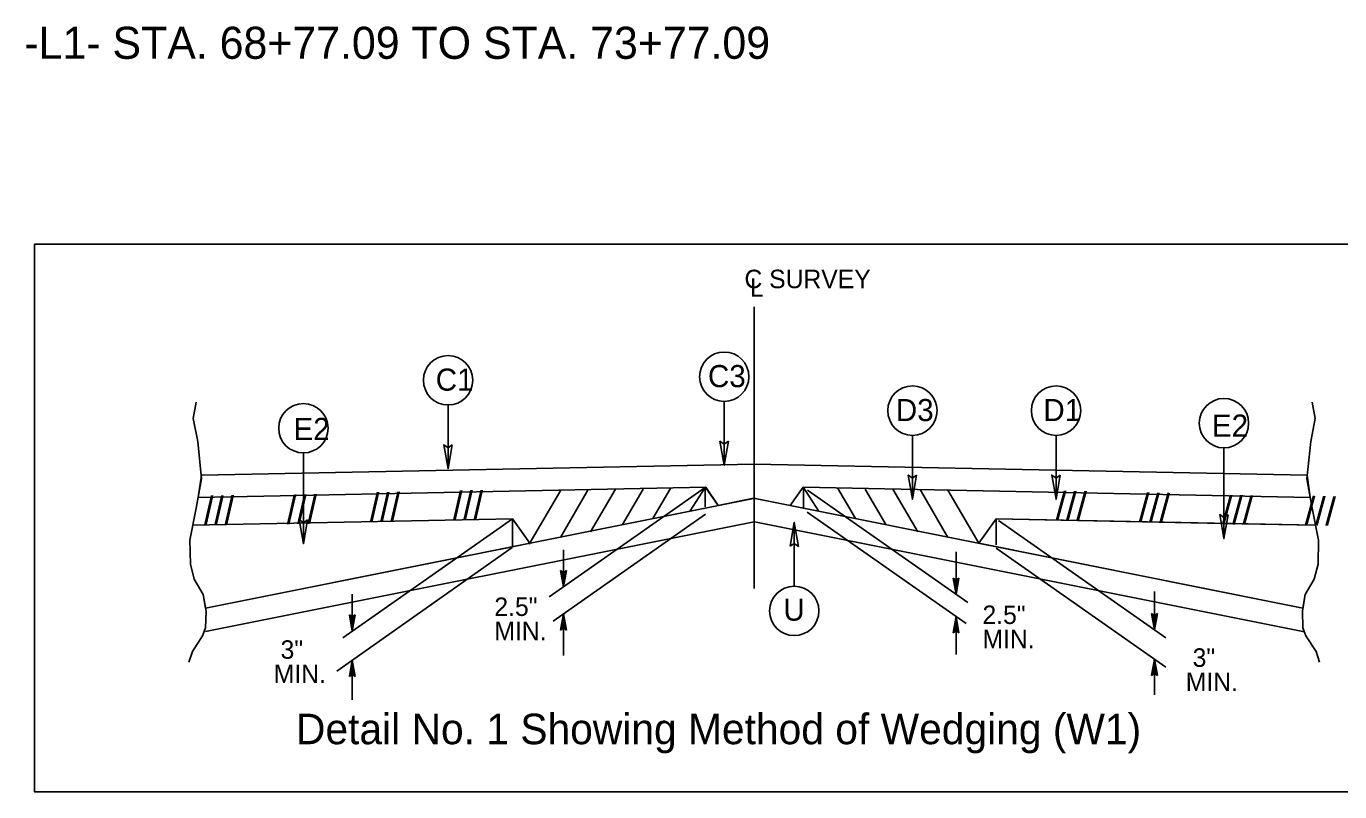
# Model space of a CAD drawing. Extents: x 573813 to 575363, y -54752 to -53123.
# Drawn here: x 574725.3 to 574799.8, y -53244.6 to -53201.2 of the extents above; entities that cross this region are included whole.
import ezdxf

# ---------------------------------------------------------------- set-up
doc = ezdxf.new("R2010")
doc.units = 0
for name, color, linetype in [('Old_Level_1', 7, 'Continuous'), ('Prop Pavement Schedule Description CELL', 7, 'Continuous'), ('Typical Detail Wedge2 CELL', 7, 'Continuous'), ('Typical ID Circle CELL', 7, 'Continuous'), ('Typical Terminator CELL', 7, 'Continuous'), ('Typical Text Centerline CELL', 7, 'Continuous'), ('Typical Text General CELL', 7, 'Continuous'), ('Typical Text ID Circle CELL', 7, 'Continuous')]:
    doc.layers.add(name, color=color, linetype=linetype)

msp = doc.modelspace()

# ---------------------------------------------------------------- linework, layer by layer
at = {"layer": 'Prop Pavement Schedule Description CELL'}
msp.add_lwpolyline([(574725.715, -53213.526), (574805.217, -53213.526), (574805.217, -53244.59), (574725.715, -53244.59)], close=True, dxfattribs=at)
at = {"layer": 'Typical Detail Wedge2 CELL'}
for p, q in [((574766.569, -53233.07), (574766.569, -53217.083)), ((574766.569, -53233.07), (574766.569, -53222.151)), ((574735.013, -53227.895), (574735.192, -53226.634)), ((574766.568, -53226.007), (574735.192, -53226.634)), ((574735.192, -53226.634), (574766.568, -53226.007)), ((574766.568, -53226.007), (574797.946, -53226.634)), ((574766.571, -53226.007), (574797.946, -53226.634)), ((574797.946, -53226.634), (574798.126, -53227.895)), ((574763.815, -53227.319), (574735.013, -53227.895)), ((574763.815, -53227.319), (574735.013, -53227.895)), ((574763.78, -53227.342), (574754.939, -53233.534)), ((574758.702, -53227.422), (574757.285, -53229.85)), ((574760.264, -53227.425), (574759.089, -53229.436)), ((574761.838, -53227.344), (574760.815, -53229.099)), ((574762.924, -53228.661), (574763.775, -53227.331)), ((574763.775, -53227.331), (574763.775, -53228.424)), ((574764.52, -53228.353), (574763.815, -53227.319)), ((574763.815, -53227.352), (574764.52, -53228.353)), ((574769.344, -53227.319), (574768.616, -53228.353)), ((574769.344, -53227.319), (574768.616, -53228.353)), ((574769.298, -53227.342), (574769.343, -53227.344)), ((574769.344, -53227.319), (574798.126, -53227.895)), ((574798.126, -53227.895), (574769.344, -53227.319)), ((574770.214, -53228.661), (574769.362, -53227.331)), ((574769.362, -53227.331), (574769.362, -53228.535)), ((574771.298, -53227.344), (574772.322, -53229.099)), ((574772.873, -53227.425), (574774.047, -53229.436)), ((574774.434, -53227.422), (574775.852, -53229.85)), ((574766.615, -53227.936), (574735.427, -53234.175)), ((574755.586, -53227.484), (574753.803, -53230.54)), ((574757.152, -53227.452), (574755.574, -53230.161)), ((574766.521, -53227.936), (574764.52, -53228.353)), ((574766.521, -53227.936), (574797.711, -53234.175)), ((574768.616, -53228.353), (574766.521, -53227.936)), ((574769.584, -53227.486), (574778.692, -53233.865)), ((574775.985, -53227.452), (574777.564, -53230.161)), ((574777.552, -53227.484), (574779.308, -53230.495)), ((574763.8, -53228.855), (574755.149, -53234.912)), ((574769.571, -53228.726), (574778.59, -53235.041)), ((574752.842, -53229.112), (574734.707, -53229.475)), ((574734.707, -53229.475), (574752.842, -53229.112)), ((574766.556, -53229.279), (574735.416, -53235.508)), ((574752.842, -53229.112), (574743.213, -53235.855)), ((574753.828, -53230.498), (574752.842, -53229.112)), ((574752.842, -53229.112), (574752.842, -53230.694)), ((574752.842, -53229.112), (574753.826, -53230.495)), ((574766.58, -53229.279), (574797.793, -53235.523)), ((574780.294, -53229.112), (574779.308, -53230.495)), ((574779.31, -53230.495), (574780.294, -53229.112)), ((574780.294, -53229.112), (574798.43, -53229.475)), ((574780.294, -53229.112), (574780.294, -53230.582)), ((574793.228, -53229.371), (574780.294, -53229.112)), ((574780.441, -53229.214), (574789.938, -53235.865)), ((574798.43, -53229.475), (574793.228, -53229.371)), ((574752.834, -53230.744), (574742.88, -53237.749)), ((574752.842, -53230.692), (574749.684, -53231.324)), ((574753.826, -53230.495), (574752.842, -53230.692)), ((574755.744, -53230.866), (574755.744, -53232.969)), ((574778.026, -53230.987), (574778.026, -53233.398)), ((574779.308, -53230.495), (574783.454, -53231.324)), ((574780.294, -53230.774), (574789.922, -53237.518)), ((574749.684, -53231.324), (574735.427, -53234.175)), ((574783.454, -53231.324), (574797.711, -53234.175)), ((574755.744, -53232.969), (574755.582, -53232.047)), ((574755.744, -53232.167), (574755.582, -53232.047)), ((574755.744, -53232.969), (574755.605, -53232.065)), ((574755.628, -53232.082), (574755.744, -53232.969)), ((574755.744, -53232.969), (574755.651, -53232.098)), ((574755.675, -53232.115), (574755.744, -53232.969)), ((574755.744, -53232.969), (574755.698, -53232.133)), ((574755.721, -53232.15), (574755.744, -53232.969)), ((574755.744, -53232.969), (574755.908, -53232.047)), ((574755.908, -53232.047), (574755.744, -53232.167)), ((574755.885, -53232.065), (574755.744, -53232.969)), ((574755.744, -53232.969), (574755.86, -53232.082)), ((574755.837, -53232.098), (574755.744, -53232.969)), ((574755.744, -53232.969), (574755.814, -53232.115)), ((574755.79, -53232.133), (574755.744, -53232.969)), ((574755.744, -53232.969), (574755.767, -53232.15)), ((574755.744, -53232.167), (574755.744, -53232.969)), ((574778.026, -53233.398), (574777.864, -53232.475)), ((574778.026, -53232.595), (574777.864, -53232.475)), ((574778.026, -53233.398), (574777.887, -53232.492)), ((574777.91, -53232.51), (574778.026, -53233.398)), ((574778.026, -53233.398), (574777.933, -53232.527)), ((574777.956, -53232.544), (574778.026, -53233.398)), ((574778.026, -53233.398), (574777.979, -53232.561)), ((574778.002, -53232.578), (574778.026, -53233.398)), ((574778.026, -53233.398), (574778.189, -53232.475)), ((574778.189, -53232.475), (574778.026, -53232.595)), ((574778.165, -53232.492), (574778.026, -53233.398)), ((574778.026, -53233.398), (574778.142, -53232.51)), ((574778.119, -53232.527), (574778.026, -53233.398)), ((574778.026, -53233.398), (574778.096, -53232.544)), ((574778.072, -53232.561), (574778.026, -53233.398)), ((574778.026, -53233.398), (574778.049, -53232.578)), ((574778.026, -53232.595), (574778.026, -53233.398)), ((574743.755, -53233.379), (574743.755, -53235.476)), ((574789.286, -53233.227), (574789.286, -53235.407)), ((574743.755, -53235.476), (574743.591, -53234.554)), ((574743.755, -53234.673), (574743.591, -53234.554)), ((574743.755, -53235.476), (574743.614, -53234.57)), ((574743.64, -53234.588), (574743.755, -53235.476)), ((574743.755, -53235.476), (574743.663, -53234.604)), ((574743.686, -53234.621), (574743.755, -53235.476)), ((574743.755, -53235.476), (574743.709, -53234.638)), ((574743.732, -53234.655), (574743.755, -53235.476)), ((574743.755, -53235.476), (574743.918, -53234.554)), ((574743.918, -53234.554), (574743.755, -53234.673)), ((574743.895, -53234.57), (574743.755, -53235.476)), ((574743.755, -53235.476), (574743.872, -53234.588)), ((574743.848, -53234.604), (574743.755, -53235.476)), ((574743.755, -53235.476), (574743.824, -53234.621)), ((574743.802, -53234.638), (574743.755, -53235.476)), ((574743.755, -53235.476), (574743.778, -53234.655)), ((574743.755, -53234.673), (574743.755, -53235.476)), ((574755.744, -53234.496), (574755.582, -53235.419)), ((574755.605, -53235.4), (574755.744, -53234.496)), ((574755.744, -53234.496), (574755.628, -53235.384)), ((574755.651, -53235.366), (574755.744, -53234.496)), ((574755.744, -53234.496), (574755.675, -53235.35)), ((574755.698, -53235.333), (574755.744, -53234.496)), ((574755.744, -53234.496), (574755.721, -53235.316)), ((574755.744, -53234.496), (574755.744, -53236.864)), ((574755.744, -53234.496), (574755.908, -53235.419)), ((574755.744, -53235.299), (574755.744, -53234.496)), ((574755.767, -53235.316), (574755.744, -53234.496)), ((574755.744, -53234.496), (574755.79, -53235.333)), ((574755.814, -53235.35), (574755.744, -53234.496)), ((574755.744, -53234.496), (574755.837, -53235.366)), ((574755.86, -53235.384), (574755.744, -53234.496)), ((574755.744, -53234.496), (574755.885, -53235.4)), ((574778.026, -53234.646), (574777.864, -53235.569)), ((574777.887, -53235.55), (574778.026, -53234.646)), ((574778.026, -53234.646), (574777.91, -53235.534)), ((574777.933, -53235.516), (574778.026, -53234.646)), ((574778.026, -53234.646), (574777.956, -53235.5)), ((574777.979, -53235.483), (574778.026, -53234.646)), ((574778.026, -53234.646), (574778.002, -53235.466)), ((574778.026, -53234.646), (574778.026, -53236.803)), ((574778.026, -53234.646), (574778.189, -53235.569)), ((574778.026, -53235.449), (574778.026, -53234.646)), ((574778.049, -53235.466), (574778.026, -53234.646)), ((574778.026, -53234.646), (574778.072, -53235.483)), ((574778.096, -53235.5), (574778.026, -53234.646)), ((574778.026, -53234.646), (574778.119, -53235.516)), ((574778.142, -53235.534), (574778.026, -53234.646)), ((574778.026, -53234.646), (574778.165, -53235.55)), ((574789.286, -53235.407), (574789.123, -53234.486)), ((574789.286, -53234.604), (574789.123, -53234.486)), ((574789.286, -53235.407), (574789.146, -53234.503)), ((574789.169, -53234.519), (574789.286, -53235.407)), ((574789.286, -53235.407), (574789.192, -53234.535)), ((574789.215, -53234.554), (574789.286, -53235.407)), ((574789.286, -53235.407), (574789.238, -53234.57)), ((574789.261, -53234.588), (574789.286, -53235.407)), ((574789.286, -53235.407), (574789.448, -53234.486)), ((574789.448, -53234.486), (574789.286, -53234.604)), ((574789.424, -53234.503), (574789.286, -53235.407)), ((574789.286, -53235.407), (574789.401, -53234.519)), ((574789.378, -53234.535), (574789.286, -53235.407)), ((574789.286, -53235.407), (574789.355, -53234.554)), ((574789.332, -53234.57), (574789.286, -53235.407)), ((574789.286, -53235.407), (574789.309, -53234.588)), ((574789.286, -53234.604), (574789.286, -53235.407)), ((574755.582, -53235.419), (574755.744, -53235.299)), ((574755.744, -53235.299), (574755.908, -53235.419)), ((574777.864, -53235.569), (574778.026, -53235.449)), ((574778.026, -53235.449), (574778.189, -53235.569)), ((574789.286, -53237.071), (574789.123, -53237.993)), ((574789.146, -53237.976), (574789.286, -53237.071)), ((574789.286, -53237.071), (574789.169, -53237.959)), ((574789.192, -53237.942), (574789.286, -53237.071)), ((574789.286, -53237.071), (574789.215, -53237.924)), ((574789.238, -53237.907), (574789.286, -53237.071)), ((574789.286, -53237.071), (574789.261, -53237.891)), ((574789.286, -53237.071), (574789.286, -53239.096)), ((574789.286, -53237.071), (574789.448, -53237.993)), ((574789.286, -53237.872), (574789.286, -53237.071)), ((574789.309, -53237.891), (574789.286, -53237.071)), ((574789.286, -53237.071), (574789.332, -53237.907)), ((574789.355, -53237.924), (574789.286, -53237.071)), ((574789.286, -53237.071), (574789.378, -53237.942)), ((574789.401, -53237.959), (574789.286, -53237.071)), ((574789.286, -53237.071), (574789.424, -53237.976)), ((574743.755, -53237.135), (574743.591, -53238.058)), ((574743.617, -53238.041), (574743.755, -53237.135)), ((574743.755, -53237.135), (574743.64, -53238.023)), ((574743.663, -53238.006), (574743.755, -53237.135)), ((574743.755, -53237.135), (574743.686, -53237.989)), ((574743.709, -53237.973), (574743.755, -53237.135)), ((574743.755, -53237.135), (574743.732, -53237.956)), ((574743.755, -53237.135), (574743.755, -53239.378)), ((574743.755, -53237.135), (574743.918, -53238.058)), ((574743.755, -53237.938), (574743.755, -53237.135)), ((574743.778, -53237.956), (574743.755, -53237.135)), ((574743.755, -53237.135), (574743.802, -53237.973)), ((574743.825, -53237.989), (574743.755, -53237.135)), ((574743.755, -53237.135), (574743.848, -53238.006)), ((574743.872, -53238.023), (574743.755, -53237.135)), ((574743.755, -53237.135), (574743.895, -53238.041)), ((574789.123, -53237.993), (574789.286, -53237.872)), ((574789.286, -53237.872), (574789.448, -53237.993)), ((574743.591, -53238.058), (574743.755, -53237.938)), ((574743.755, -53237.938), (574743.918, -53238.058))]:
    msp.add_line(p, q, dxfattribs=at)
for points in [[(574734.9, -53222.493), (574734.732, -53223.412), (574734.984, -53224.719), (574735.205, -53226.835), (574734.9, -53228.505), (574734.539, -53230.313), (574734.566, -53231.678), (574734.789, -53232.54), (574735.291, -53233.404), (574735.457, -53234.35), (574735.429, -53235.295), (574735.262, -53235.742), (574734.678, -53236.632), (574734.483, -53237.245)], [(574798.237, -53222.493), (574798.404, -53223.412), (574798.154, -53224.719), (574797.931, -53226.835), (574798.237, -53228.505), (574798.599, -53230.313), (574798.571, -53231.678), (574798.347, -53232.54), (574797.847, -53233.404), (574797.681, -53234.35), (574797.707, -53235.295), (574797.874, -53235.742), (574798.458, -53236.632), (574798.653, -53237.245)], [(574735.426, -53234.175), (574735.291, -53233.404), (574734.789, -53232.54), (574734.566, -53231.678), (574734.539, -53230.313), (574734.706, -53229.475)], [(574797.711, -53234.175), (574797.847, -53233.404), (574798.347, -53232.54), (574798.571, -53231.678), (574798.599, -53230.313), (574798.43, -53229.475)]]:
    msp.add_lwpolyline(points, dxfattribs=at)
at = {"layer": 'Typical ID Circle CELL'}
for p, q in [((574749.195, -53222.652), (574749.195, -53226.274)), ((574764.865, -53222.45), (574764.865, -53226.072)), ((574775.547, -53224.375), (574775.547, -53227.997)), ((574783.699, -53224.375), (574783.699, -53227.997)), ((574793.228, -53225.086), (574793.228, -53230.236)), ((574740.981, -53225.373), (574740.981, -53230.523)), ((574768.839, -53232.932), (574768.839, -53229.31))]:
    msp.add_line(p, q, dxfattribs=at)
for centre in [(574749.195, -53221.251), (574764.865, -53221.049), (574775.548, -53222.974), (574783.699, -53222.974), (574740.98, -53223.972), (574793.228, -53223.685), (574768.839, -53234.333)]:
    msp.add_circle(centre, 1.401, dxfattribs=at)
at = {"layer": 'Typical Terminator CELL'}
for points in [[(574749.429, -53224.915), (574749.195, -53226.274), (574748.953, -53224.908), (574749.195, -53225.081)], [(574749.429, -53224.915), (574749.195, -53226.274), (574748.953, -53224.908), (574749.195, -53225.081)], [(574765.099, -53224.713), (574764.865, -53226.072), (574764.623, -53224.706), (574764.865, -53224.879)], [(574765.099, -53224.713), (574764.865, -53226.072), (574764.623, -53224.706), (574764.865, -53224.879)], [(574775.781, -53226.638), (574775.547, -53227.997), (574775.306, -53226.631), (574775.547, -53226.805)], [(574775.781, -53226.638), (574775.547, -53227.997), (574775.306, -53226.631), (574775.547, -53226.805)], [(574783.933, -53226.638), (574783.699, -53227.997), (574783.458, -53226.631), (574783.699, -53226.805)], [(574783.933, -53226.638), (574783.699, -53227.997), (574783.458, -53226.631), (574783.699, -53226.805)], [(574793.462, -53228.877), (574793.228, -53230.236), (574792.987, -53228.87), (574793.228, -53229.043)], [(574741.215, -53229.165), (574740.981, -53230.523), (574740.739, -53229.157), (574740.981, -53229.331)], [(574741.215, -53229.165), (574740.981, -53230.523), (574740.739, -53229.157), (574740.981, -53229.331)], [(574768.605, -53230.669), (574768.839, -53229.31), (574769.08, -53230.676), (574768.839, -53230.503)], [(574768.605, -53230.669), (574768.839, -53229.31), (574769.08, -53230.676), (574768.839, -53230.503)]]:
    msp.add_lwpolyline(points, close=True, dxfattribs=at)

# ---------------------------------------------------------------- texts
at = {"layer": 'Old_Level_1'}
msp.add_text('-L1- STA. 68+77.09 TO STA. 73+77.09', height=1.81916, rotation=0, dxfattribs=at).set_placement((574725.144, -53203.018))
at = {"layer": 'Typical Detail Wedge2 CELL'}
for height, rotation, p in [(1.5735, 1.14473, (574735.331, -53229.453)), (1.5735, 1.14639, (574740.034, -53229.398)), (1.5728, 1.14453, (574744.747, -53229.259)), (1.5729, 1.14629, (574749.465, -53229.162)), (1.5729, 358.85527, (574783.673, -53229.162)), (1.5729, 358.85361, (574788.39, -53229.259)), (1.5735, 358.85537, (574793.102, -53229.398)), (1.5735, 358.85371, (574797.805, -53229.453))]:
    msp.add_text('/// ', height=height, rotation=rotation, dxfattribs=at).set_placement(p)
for s, p in [('2.5"', (574751.82, -53234.62)), ('2.5"', (574779.524, -53235.076)), ('MIN.', (574751.82, -53235.994)), ('MIN.', (574779.524, -53236.45)), (' 3"', (574739.297, -53237.051)), (' 3"', (574791.061, -53237.506)), ('MIN.', (574739.297, -53238.425)), ('MIN.', (574791.061, -53238.88))]:
    msp.add_text(s, height=1.0482, dxfattribs=at).set_placement(p)
at = {"layer": 'Typical Text Centerline CELL'}
for s, height, p in [('C SURVEY ', 1.0482, (574766.014, -53216.028)), ('L', 1.048, (574766.321, -53216.518))]:
    msp.add_text(s, height=height, dxfattribs=at).set_placement(p)
at = {"layer": 'Typical Text General CELL'}
msp.add_text('Detail No. 1 Showing Method of Wedging (W1)', height=1.73023, dxfattribs=at).set_placement((574740.561, -53241.896))
at = {"layer": 'Typical Text ID Circle CELL'}
for s, height, p in [('C1', 1.2544, (574748.492, -53221.842)), ('C3', 1.2544, (574763.942, -53221.642)), ('D3', 1.2544, (574774.606, -53223.567)), ('D1', 1.2544, (574782.978, -53223.567)), ('E2', 1.2544, (574740.418, -53224.639)), ('E2', 1.2544, (574792.546, -53224.448)), ('U', 1.254, (574768.226, -53234.888))]:
    msp.add_text(s, height=height, dxfattribs=at).set_placement(p)

doc.saveas('drawing.dxf')
